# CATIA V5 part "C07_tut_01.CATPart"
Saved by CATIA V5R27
Part number: Part1
Bounding box of the stored display mesh (mm): x -150 to 150, y -150 to 150, z -127.69 to 0
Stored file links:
  E:\_Deepak\2017_Deepak\CATIA\Resources\Tutorial Files\Tutorials\c07_catia_v5_6r2016_tut\C07_tut_01.CATPart
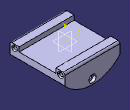
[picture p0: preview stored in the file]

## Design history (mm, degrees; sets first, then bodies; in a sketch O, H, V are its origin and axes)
Body1 (main body)
  Sketch1 on zx-plane, origin (0, 0, 0), H (-1, 0, 0), V (0, 0, 1)
    point P1 (-150, 0)
    line L1 (-150, 0) -> (150, 0)
    point P2 (150, 0)
    line L2 (150, 0) -> (150, -60)
    point P3 (150, -60)
    point P4 (-150, -60)
    point P5 (-150, 0)
    line L3 (-150, 0) -> (-150, -60)
    arc A1 centre (0, 72.2876) radius 200 from (150, -60) to (-150, -60) cw
    point P7 (0, -127.7124)
    length L1 = 300
    length L2 = 60
    radius A1 = 200
    horizontal: L1 H
    vertical: L2 V
    symmetry: P1 P2 V, P3 P4 V, P2 P5 V, L2 L3 V
    coincidence: L1 H, A1 P7, P7 V, P1 P5
  Pad1: profile Sketch1, direction (0, 1, 0), length 150, mirrored extent
  Sketch2 on yz-plane, origin (0, 0, 0), H (0, 1, 0), V (0, 0, 1)
    line L1 (100, 0) -> (-100, 0)
    reference projected line E1 (-150, 0) -> (150, 0) from edge [face of Pad1 from Sketch1.L3 | face of Pad1 from Sketch1.L1]
    line L2 (-100, 0) -> (-100, -25)
    line L3 (-100, -25) -> (100, -25)
    line L4 (100, -25) -> (100, 0)
    length L1 = 200
    length L4 = 25
    distance V L4 = 100
    horizontal: L1 H, L3 H
    coincidence: L1 E1
    vertical: L2 V, L4 V
  Pocket1: profile Sketch2, direction (-1, 0, 0), length 150, mirrored extent
  Fillet1: radius 10, on edge [start face of Pad1 | face of Pad1 from Sketch1.L1]; edge [face of Pad1 from Sketch1.L1 | end face of Pad1]
  Sketch3 on yz-plane, origin (0, 0, 0), H (0, 1, 0), V (0, 0, 1)
    point P1 (-125, -20)
    point P2 (125, -20)
    reference projected line E1 (150, 0) -> (150, -60) from edge [face of Pad1 from Sketch1.L3 | end face of Pad1]
    reference projected line E2 (-150, 0) -> (150, 0) from edge [face of Pad1 from Sketch1.L3 | face of Pad1 from Sketch1.L1]
    distance P2 E1 = 25
    distance P2 E2 = 20
    symmetry: P1 P2 V
  Sketch4 on face of Pad1 from Sketch1.L3, origin (150, 125, -20), H (0, 1, 0), V (0, 0, 1)
    point P1 (0, 0)
    reference projected point E1 (0, 0) from Sketch3.P2
    coincidence: E1 P1
  Hole1: placed by Sketch4, at (150, 125, -20) direction (-1, 0, 0), diameter 20, through (limit type 3), countersink depth 5, countersink angle 90
  Sketch5 on face of Pad1 from Sketch1.L3, origin (150, -125, -20), H (0, 1, 0), V (0, 0, 1)
    point P1 (0, 0)
    reference projected point E1 (0, 0) from Sketch3.P1
    coincidence: E1 P1
  Hole2: placed by Sketch5, at (150, -125, -20) direction (-1, 0, 0), diameter 20, through (limit type 3), countersink depth 5, countersink angle 90
  Sketch6 on zx-plane, origin (0, 0, 0), H (-1, 0, 0), V (0, 0, 1)
    point P1 (0, -100)
    distance P1 H = 100
    coincidence: P1 V
  Sketch7 on end face of Pad1, origin (0, 150, -100), H (1, 0, 0), V (0, 0, -1)
    point P1 (0, 0)
    reference projected point E1 (0, 0) from Sketch6.P1
    coincidence: E1 P1
  Hole3: placed by Sketch7, at (0, 150, -100) direction (0, -1, 0), diameter 20, through (limit type 3), counterbore diameter 40, counterbore depth 15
